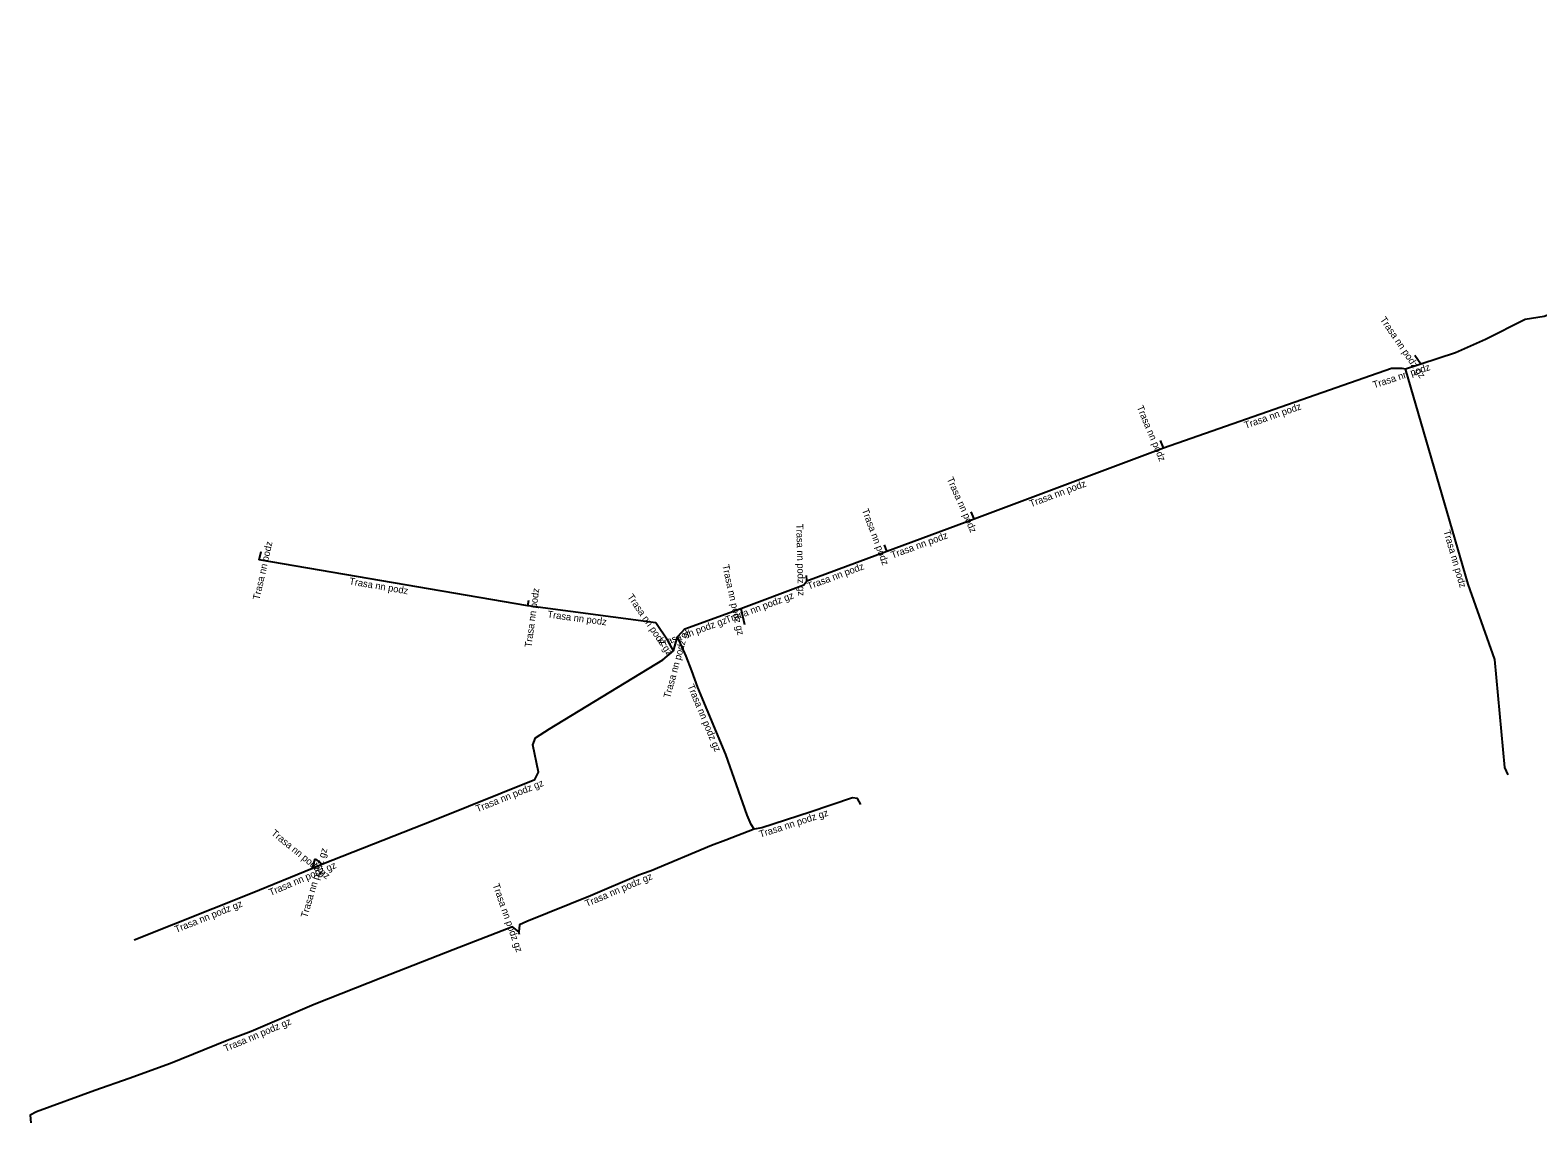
# Model space of a CAD drawing. Extents: x -703044 to -702068, y -1022301 to -1021908.
# Drawn here: x -703043.5 to -702935.6, y -1022028.5 to -1021950.2 of the extents above; entities that cross this region are included whole.
import ezdxf

# ---------------------------------------------------------------- set-up
doc = ezdxf.new("R2010")
doc.units = 0
doc.layers.add('Popiskový text - Ostatní atributy Trasy', color=7, linetype='Continuous')
doc.layers.add('Spojnice NN', color=7, linetype='Continuous')

msp = doc.modelspace()

# ---------------------------------------------------------------- linework, layer by layer
at = {"layer": 'Spojnice NN'}
for points in [[(-702943.94, -1021974.08), (-702941.45, -1021973.27), (-702939.31, -1021972.32), (-702936.46, -1021970.88), (-702935.11, -1021970.67), (-702931.21, -1021969.19), (-702926.13, -1021967.34), (-702925.03, -1021967.29), (-702923.04, -1021966.64), (-702920.41, -1021965.77), (-702912.7, -1021962.97), (-702911.89, -1021962.17), (-702904.3, -1021959.41), (-702896.85, -1021956.74), (-702887.69, -1021953.43), (-702878.2, -1021950.19)], [(-702944.37, -1021973.46), (-702943.94, -1021974.08)], [(-702962.35, -1021980.1), (-702946.03, -1021974.41), (-702945.29, -1021974.41), (-702945.04, -1021974.44)], [(-702945.04, -1021974.44), (-702943.94, -1021974.08)], [(-702937.67, -1022003.52), (-702937.91, -1022002.99), (-702938.63, -1021995.26), (-702940.54, -1021989.88), (-702945.04, -1021974.44)], [(-702975.92, -1021985.19), (-702962.35, -1021980.1)], [(-702962.35, -1021980.1), (-702962.58, -1021979.58)], [(-702975.92, -1021985.19), (-702976.13, -1021984.7)], [(-702982.17, -1021987.5), (-702975.92, -1021985.19)], [(-703027.11, -1021988.12), (-703026.97, -1021987.52)], [(-702987.91, -1021989.63), (-702982.17, -1021987.5)], [(-702982.17, -1021987.5), (-702982.33, -1021987.06)], [(-703007.87, -1021991.42), (-703027.11, -1021988.12)], [(-702992.62, -1021991.61), (-702988.12, -1021989.92), (-702987.91, -1021989.63)], [(-702987.91, -1021989.63), (-702987.92, -1021989.24)], [(-703007.87, -1021991.42), (-703007.82, -1021991.01)], [(-702998.72, -1021992.64), (-703007.87, -1021991.42)], [(-702997.16, -1021993.63), (-702996.64, -1021993.08), (-702992.62, -1021991.61)], [(-702992.62, -1021991.61), (-702992.37, -1021992.76)], [(-702997.44, -1021994.65), (-702997.82, -1021993.95), (-702998.72, -1021992.64)], [(-702997.44, -1021994.65), (-702997.16, -1021993.63)], [(-702991.67, -1022007.41), (-702991.89, -1022007.08), (-702992.17, -1022006.42), (-702993.71, -1022002.06), (-702995.71, -1021997.27), (-702996.14, -1021996.08), (-702996.54, -1021995.02), (-702997.16, -1021993.63)], [(-703022.63, -1022009.93), (-703014.56, -1022006.74), (-703007.38, -1022003.87), (-703007.11, -1022003.33), (-703007.52, -1022001.38), (-703007.33, -1022000.88), (-703006.33, -1022000.22), (-702998.21, -1021995.29), (-702997.44, -1021994.65)], [(-702984.03, -1022005.66), (-702984.28, -1022005.23), (-702984.62, -1022005.17), (-702987.66, -1022006.19), (-702991.12, -1022007.31), (-702991.67, -1022007.41)], [(-702991.67, -1022007.41), (-702993.71, -1022008.2), (-702994.72, -1022008.58), (-702999.06, -1022010.4), (-702999.67, -1022010.61), (-702999.93, -1022010.7), (-703003.4, -1022012.18), (-703007.96, -1022014.03), (-703008.48, -1022014.27), (-703008.53, -1022014.78)], [(-703036.07, -1022015.35), (-703027.63, -1022011.98), (-703023.31, -1022010.22)], [(-703023.31, -1022010.22), (-703023.11, -1022009.54)], [(-703023.31, -1022010.22), (-703022.63, -1022009.93)], [(-703023.11, -1022009.54), (-703022.63, -1022009.93)], [(-703008.53, -1022014.78), (-703008.98, -1022014.42), (-703013.22, -1022016.07), (-703018.29, -1022018.05), (-703023.17, -1022019.98), (-703027.7, -1022021.9), (-703029.42, -1022022.56), (-703033.48, -1022024.21), (-703036.42, -1022025.28), (-703038.88, -1022026.13), (-703043.06, -1022027.66), (-703043.52, -1022027.91), (-703043.48, -1022028.45)], [(-703008.47, -1022014.95), (-703008.53, -1022014.78)]]:
    msp.add_lwpolyline(points, dxfattribs=at)

# ---------------------------------------------------------------- texts
at = {"layer": 'Popiskový text - Ostatní atributy Trasy'}
for s, rotation, p in [('Trasa nn podz gz', 304.294, (-702946.88, -1021970.92)), ('Trasa nn podz', 18.1013, (-702947.28, -1021975.85)), ('Trasa nn podz', 292.8926, (-702964.29, -1021977.19)), ('Trasa nn podz', 19.2069, (-702956.48, -1021978.74)), ('Trasa nn podz', 293.9087, (-702977.89, -1021982.33)), ('Trasa nn podz', 20.5968, (-702971.85, -1021984.36)), ('Trasa nn podz', 290.5989, (-702983.97, -1021984.56)), ('Trasa nn podz gz', 271.4688, (-702988.66, -1021985.56)), ('Trasa nn podz', 77.2611, (-703027.1, -1021991.03)), ('Trasa nn podz', 20.227, (-702981.77, -1021988.04)), ('Trasa nn podz', 286.2519, (-702942.32, -1021986.07)), ('Trasa nn podz gz', 282.3958, (-702993.96, -1021988.52)), ('Trasa nn podz', 20.3699, (-702987.76, -1021990.27)), ('Trasa nn podz', 350.2621, (-703020.7, -1021989.88)), ('Trasa nn podz', 82.4144, (-703007.62, -1021994.42)), ('Trasa nn podz gz', 304.49, (-703000.78, -1021990.78)), ('Trasa nn podz gz', 20.5839, (-702993.62, -1021992.68)), ('Trasa nn podz', 352.4263, (-703006.5, -1021992.26)), ('Trasa nn podz gz', 20.086, (-702998.42, -1021994.42)), ('Trasa nn podz gz', 74.6499, (-702997.7, -1021998.07)), ('Trasa nn podz gz', 292.6623, (-702996.46, -1021997.16)), ('Trasa nn podz gz', 21.7876, (-703011.49, -1022006.21)), ('Trasa nn podz gz', 17.9367, (-702991.23, -1022008.03)), ('Trasa nn podz gz', 320.9061, (-703026.3, -1022007.78)), ('Trasa nn podz gz', 73.6105, (-703023.68, -1022013.8)), ('Trasa nn podz gz', 23.0968, (-703026.3, -1022012.2)), ('Trasa nn podz gz', 289.44, (-703010.41, -1022011.41)), ('Trasa nn podz gz', 23.0989, (-703003.66, -1022013)), ('Trasa nn podz gz', 21.7663, (-703033.06, -1022014.85)), ('Trasa nn podz gz', 22.9692, (-703029.53, -1022023.38))]:
    msp.add_text(s, height=0.5, rotation=rotation, dxfattribs=at).set_placement(p)

doc.saveas('drawing.dxf')
